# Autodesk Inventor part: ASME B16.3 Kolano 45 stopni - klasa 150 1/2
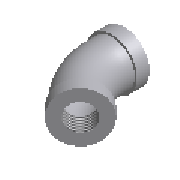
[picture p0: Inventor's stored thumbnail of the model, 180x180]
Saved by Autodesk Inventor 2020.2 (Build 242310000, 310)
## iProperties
Manager: www.cadconsulting.pl
Company: Fabian Stasiak CAD Consulting
NAME: PIPING: ASME B16.3 45 Deg Elbow - Class 150
DATA: <meta><inlinegroups number="0" deflen="0"></inlinegroups><connections number="2"></connections><angles><a>2.35619449019234</a></angles></meta>
IsCustomPart: 0
Created: 2014-02
Part Number: ASME B16.3 Kolano 45 stopni - klasa 150 1/2
Material: Żelazo, ciągliwe
Description: Kolano 45º ze stali zgrzewnej, gwintowane - klasa 150
Document SubType Name: Modeling
Standard: ASME B16.3
Designer: F.Stasiak
Standard Revision: 1988
Standards Organization: ANSI
Language: pl-PL
Size Designation: 1/2
Categories: <MemberInstance><Categories><Category DisplayName="Rury cienko- i grubościenne" InternalName="4347fa0f-2144-441d-94cd-e3e15c92b736" Mnemonic="TUBEANDPIPE"><Cate
Density: 7.15 g/cm^3
Appearance: Częściowo polerowana
Catalog Web Link: www.expertbooks.pl
Author: F.Stasiak
Subject: Zbiór ćwiczeń. Autodesk Inventor 2020. Kurs Professional
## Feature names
1. Revolution1
2. Sweep1
3. Revolution2
## Parameters: MD = 18.32077 mm, C1 = 22.352 mm, B = 10.922 mm, G = 2.54 mm, F1 = 22.86 mm, d0 = 18.32077 mm, d1 = 27.94 mm, d2 = 30.48 mm, d3 = 6.35 mm, d4 = 10.922 mm, d5 = 0.3124 mm, d16 = 90 deg, d6 = 22.86 mm, d7 = 27.94 mm, d8 = 135 deg, d9 = 22.352 mm, d10 = 11.43 mm, d11 = 0, d12 = 0.3124 mm, d13 = 10.922 mm, d14 = 6.35 mm, d15 = 18.32077 mm, d17 = 27.94 mm, d18 = 30.48 mm, d51 = 90 deg, P = 1.8143 mm, d58 = 10.922 mm, d59 = 0, d60 = 25.4 mm, d61 = 0, H = 30.48 mm, E1 = 6.35 mm, d62 = 0, Size_Designation = 5 mm
